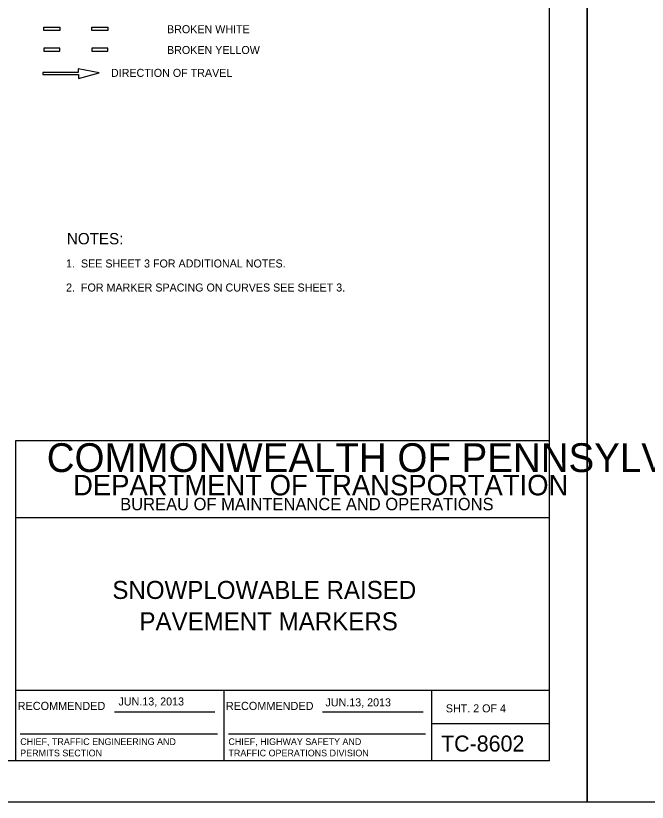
# Model space of a CAD drawing. Extents: x 639362 to 641108, y 298458 to 299646.
# Drawn here: x 639989.3 to 640225.9, y 298457.6 to 298752.3 of the extents above; entities that cross this region are included whole.
import ezdxf

# ---------------------------------------------------------------- set-up
doc = ezdxf.new("R2010")
doc.units = 0
for name, color, linetype in [('1', 7, 'Continuous'), ('2', 7, 'Continuous'), ('Level 1', 7, 'Continuous'), ('PLT-BNDY', 7, 'Continuous')]:
    doc.layers.add(name, color=color, linetype=linetype)

msp = doc.modelspace()

# ---------------------------------------------------------------- linework, layer by layer
at = {"layer": '1'}
for p, q in [((640189.27, 298473.19), (640189.27, 299037.19)), ((639989.27, 298473.19), (639989.27, 298593.19)), ((639989.27, 298593.19), (640189.27, 298593.19)), ((640189.27, 298564.19), (639989.27, 298564.19)), ((639989.27, 298499.57), (640189.27, 298499.57)), ((640067.27, 298499.57), (640067.27, 298473.19)), ((640145.15, 298473.19), (640145.15, 298499.57)), ((640026.24, 298491.57), (640063.87, 298491.57)), ((640104.24, 298491.57), (640141.87, 298491.57)), ((640145.15, 298487.19), (640189.27, 298487.19)), ((640189.27, 298473.19), (639403.27, 298473.19))]:
    msp.add_line(p, q, dxfattribs=at)
at = {"layer": '2'}
for p, q in [((639999.76, 298747.98), (640005.77, 298747.98)), ((640017.8, 298747.98), (640023.81, 298747.98)), ((640005.77, 298740.19), (639999.76, 298740.19)), ((640023.81, 298740.19), (640017.8, 298740.19)), ((640020.48, 298730.98), (640012.68, 298732.46)), ((640012.68, 298732.46), (640012.68, 298731.01)), ((640012.68, 298731.01), (639999.43, 298731.01)), ((639999.43, 298731.01), (639999.43, 298730.31)), ((639999.43, 298730.31), (640012.76, 298730.31)), ((640012.76, 298728.86), (640020.48, 298730.98)), ((640012.76, 298730.31), (640012.76, 298728.86))]:
    msp.add_line(p, q, dxfattribs=at)
for points in [[(640005.77, 298747.98), (640005.77, 298746.78), (639999.76, 298746.78), (639999.76, 298747.98)], [(640023.81, 298747.98), (640023.81, 298746.78), (640017.8, 298746.78), (640017.8, 298747.98)], [(639999.76, 298740.19), (639999.76, 298738.99), (640005.77, 298738.99), (640005.77, 298740.19)], [(640017.8, 298740.19), (640017.8, 298738.99), (640023.81, 298738.99), (640023.81, 298740.19)]]:
    msp.add_lwpolyline(points, dxfattribs=at)
at = {"layer": 'Level 1'}
for p, q in [((639990.96, 298483.24), (640064.83, 298483.24)), ((640068.96, 298483.24), (640142.83, 298483.24))]:
    msp.add_line(p, q, dxfattribs=at)
at = {"layer": 'PLT-BNDY'}
for points in [[(639362.31, 299051.63), (640203.31, 299051.63), (640203.31, 298457.63), (639362.31, 298457.63)], [(640203.31, 299051.63), (641044.31, 299051.63), (641044.31, 298457.63), (640203.31, 298457.63)]]:
    msp.add_lwpolyline(points, close=True, dxfattribs=at)

# ---------------------------------------------------------------- texts
at = {"layer": '1'}
for s, height, p in [('COMMONWEALTH OF PENNSYLVANIA', 10.7828, (640000.9, 298581.36)), ('DEPARTMENT OF TRANSPORTATION', 7.6837, (640010.76, 298572.61)), ('BUREAU OF MAINTENANCE AND OPERATIONS', 4.6253, (640028.41, 298567.04)), ('SNOWPLOWABLE RAISED', 6.75, (640025.46, 298533.81)), ('PAVEMENT MARKERS', 6.75, (640035.61, 298522.06)), ('JUN.13, 2013', 3, (640027.78, 298493.89)), ('JUN.13, 2013', 3, (640105.31, 298493.56)), ('RECOMMENDED', 3.048, (639989.99, 298492.2)), ('RECOMMENDED', 3.048, (640067.99, 298492.2)), ('SHT. 2 OF 4', 3, (640150.4, 298491.31)), ('TC-8602', 6, (640148.6, 298476.63))]:
    msp.add_text(s, height=height, dxfattribs=at).set_placement(p)
at = {"layer": '2'}
for s, height, p in [('BROKEN WHITE', 3, (640045.95, 298745.77)), ('BROKEN YELLOW', 3, (640045.95, 298737.98)), ('DIRECTION OF TRAVEL', 3, (640024.95, 298729.41)), ('NOTES:', 4.25, (640008.44, 298666.67)), ('1.  SEE SHEET 3 FOR ADDITIONAL NOTES.', 3, (640008.13, 298657.99)), ('2.  FOR MARKER SPACING ON CURVES SEE SHEET 3.', 3, (640008.13, 298648.99))]:
    msp.add_text(s, height=height, dxfattribs=at).set_placement(p)
at = {"layer": 'Level 1'}
for s, p in [('CHIEF, TRAFFIC ENGINEERING AND', (639990.96, 298479.08)), ('CHIEF, HIGHWAY SAFETY AND', (640068.96, 298479.08)), ('PERMITS SECTION', (639990.96, 298474.83)), ('TRAFFIC OPERATIONS DIVISION', (640068.96, 298474.83))]:
    msp.add_text(s, height=2.5, dxfattribs=at).set_placement(p)

doc.saveas('drawing.dxf')
